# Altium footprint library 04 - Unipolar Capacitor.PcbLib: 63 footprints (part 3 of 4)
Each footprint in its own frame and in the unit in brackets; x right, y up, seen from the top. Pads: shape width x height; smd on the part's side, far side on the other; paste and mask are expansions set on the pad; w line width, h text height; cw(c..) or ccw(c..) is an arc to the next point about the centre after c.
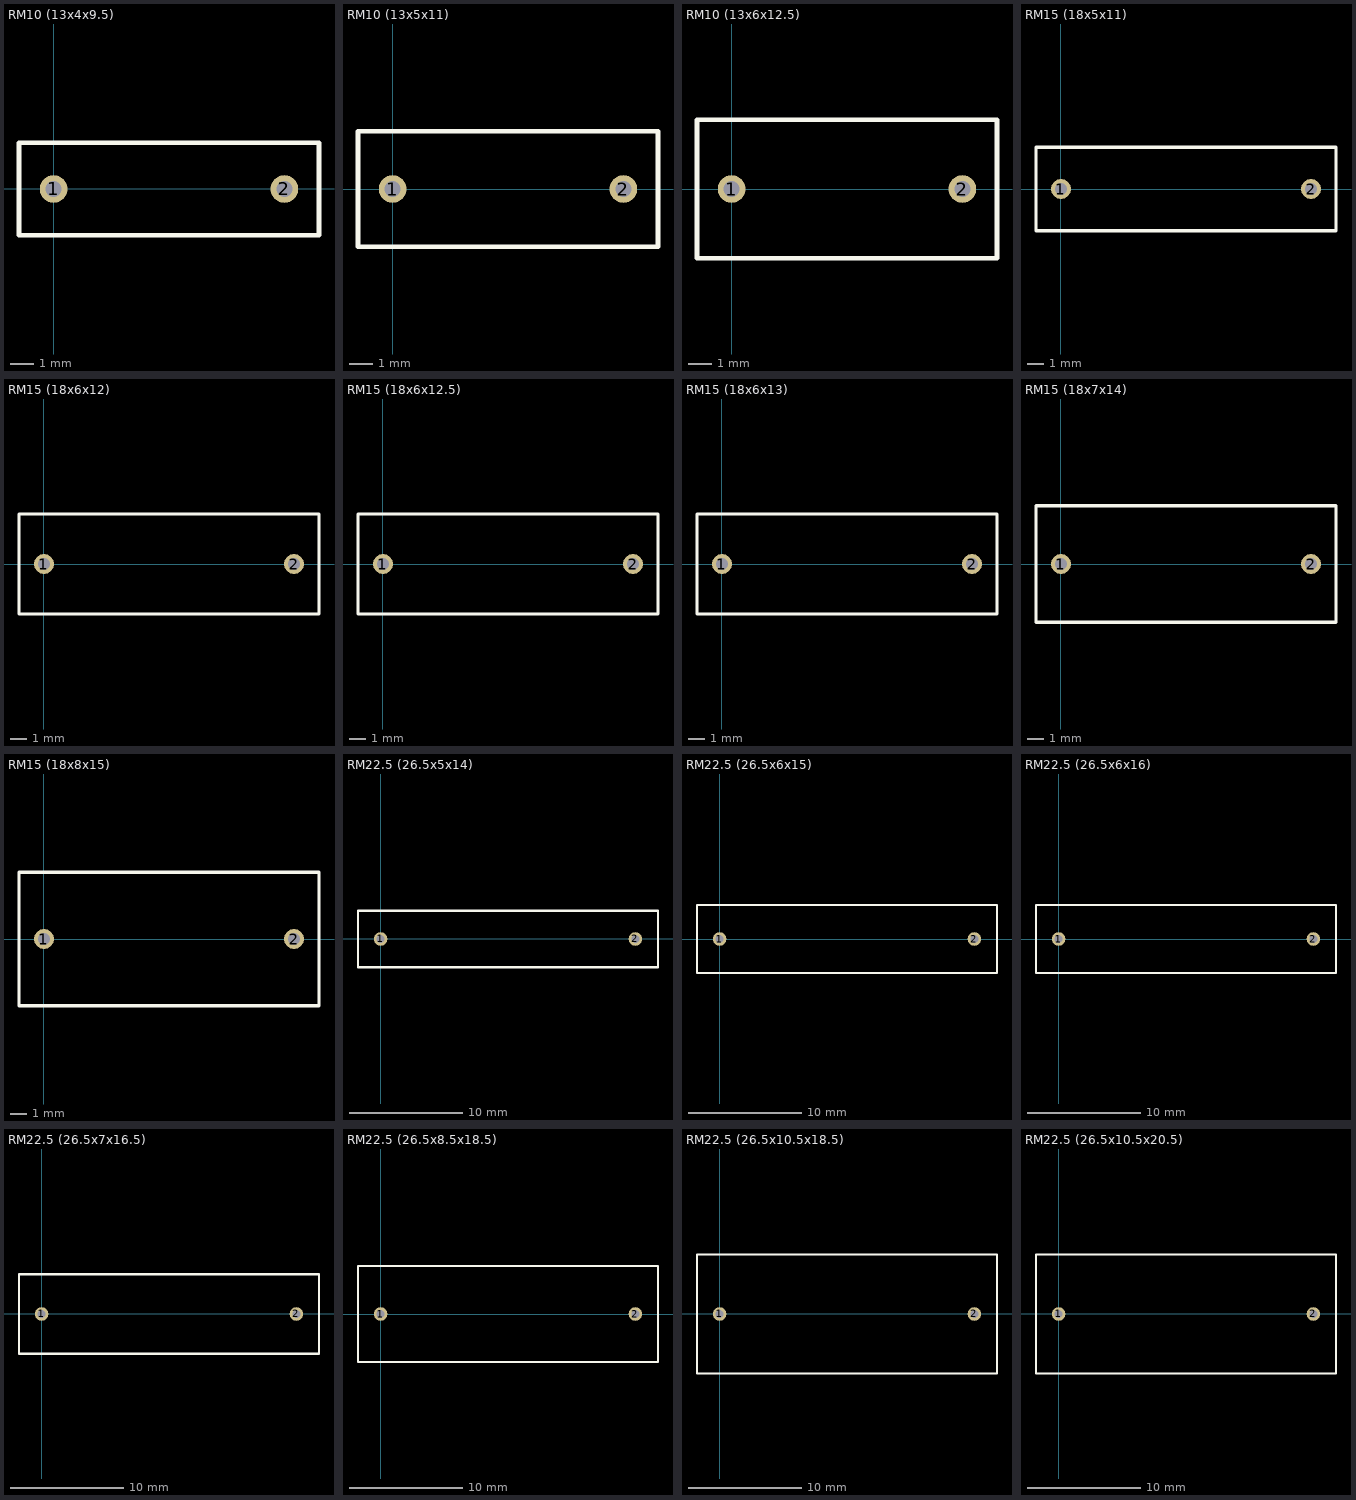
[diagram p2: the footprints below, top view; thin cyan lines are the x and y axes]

## RM10 (13x4x9.5) [mm] "Radial Thumb Capacitor"
height 9.5
pads (2):
  round 1.2 hole 0.7: 1(0,0) 2(10,0)
Top Overlay:
  lines w0.2: -1.5,-2 11.5,-2 11.5,2 -1.5,2 -1.5,-2

## RM10 (13x5x11) [mm] "Radial Thumb Capacitor"
height 11
pads (2):
  round 1.2 hole 0.7: 1(0,0) 2(10,0)
Top Overlay:
  lines w0.2: -1.5,-2.5 11.5,-2.5 11.5,2.5 -1.5,2.5 -1.5,-2.5

## RM10 (13x6x12.5) [mm] "Radial Thumb Capacitor"
height 12.5
pads (2):
  round 1.2 hole 0.7: 1(0,0) 2(10,0)
Top Overlay:
  lines w0.2: -1.5,-3 11.5,-3 11.5,3 -1.5,3 -1.5,-3

## RM15 (18x5x11) [mm] "Radial Thumb Capacitor"
height 11
pads (2):
  round 1.2 hole 0.7: 1(0,0) 2(15,0)
Top Overlay:
  lines w0.2: -1.5,-2.5 16.5,-2.5 16.5,2.5 -1.5,2.5 -1.5,-2.5

## RM15 (18x6x12) [mm] "Radial Thumb Capacitor"
height 12
pads (2):
  round 1.2 hole 0.7: 1(0,0) 2(15,0)
Top Overlay:
  lines w0.2: -1.5,-3 -1.5,3 16.5,3 16.5,-3 -1.5,-3

## RM15 (18x6x12.5) [mm] "Radial Thumb Capacitor"
height 12.5
pads (2):
  round 1.2 hole 0.7: 1(0,0) 2(15,0)
Top Overlay:
  lines w0.2: -1.5,-3 16.5,-3 16.5,3 -1.5,3 -1.5,-3

## RM15 (18x6x13) [mm] "Radial Thumb Capacitor"
height 13
pads (2):
  round 1.2 hole 0.7: 1(0,0) 2(15,0)
Top Overlay:
  lines w0.2: -1.5,-3 -1.5,3 16.5,3 16.5,-3 -1.5,-3

## RM15 (18x7x14) [mm] "Radial Thumb Capacitor"
height 14
pads (2):
  round 1.2 hole 0.7: 1(0,0) 2(15,0)
Top Overlay:
  lines w0.2: -1.5,-3.5 16.5,-3.5 16.5,3.5 -1.5,3.5 -1.5,-3.5

## RM15 (18x8x15) [mm] "Radial Thumb Capacitor"
height 15
pads (2):
  round 1.2 hole 0.7: 1(0,0) 2(15,0)
Top Overlay:
  lines w0.2: -1.5,-4 16.5,-4 16.5,4 -1.5,4 -1.5,-4

## RM22.5 (26.5x5x14) [mm] "Radial Thumb Capacitor"
height 14
pads (2):
  round 1.2 hole 0.7: 1(0,0) 2(22.5,0)
Top Overlay:
  lines w0.2: -2,-2.5 -2,2.5 24.5,2.5 24.5,-2.5 -2,-2.5

## RM22.5 (26.5x6x15) [mm] "Radial Thumb Capacitor"
height 15
pads (2):
  round 1.2 hole 0.7: 1(0,0) 2(22.5,0)
Top Overlay:
  lines w0.2: -2,-3 24.5,-3 24.5,3 -2,3 -2,-3

## RM22.5 (26.5x6x16) [mm] "Radial Thumb Capacitor"
height 16
pads (2):
  round 1.2 hole 0.7: 1(0,0) 2(22.5,0)
Top Overlay:
  lines w0.2: -2,-3 24.5,-3 24.5,3 -2,3 -2,-3

## RM22.5 (26.5x7x16.5) [mm] "Radial Thumb Capacitor"
height 16.5
pads (2):
  round 1.2 hole 0.7: 1(0,0) 2(22.5,0)
Top Overlay:
  lines w0.2: -2,-3.5 24.5,-3.5 24.5,3.5 -2,3.5 -2,-3.5

## RM22.5 (26.5x8.5x18.5) [mm] "Radial Thumb Capacitor"
height 18.5
pads (2):
  round 1.2 hole 0.7: 1(0,0) 2(22.5,0)
Top Overlay:
  lines w0.2: -2,-4.25 24.5,-4.25 24.5,4.25 -2,4.25 -2,-4.25

## RM22.5 (26.5x10.5x18.5) [mm] "Radial Thumb Capacitor"
height 18.5
pads (2):
  round 1.2 hole 0.7: 1(0,0) 2(22.5,0)
Top Overlay:
  lines w0.2: -2,-5.25 24.5,-5.25 24.5,5.25 -2,5.25 -2,-5.25

## RM22.5 (26.5x10.5x20.5) [mm] "Radial Thumb Capacitor"
height 20.5
pads (2):
  round 1.2 hole 0.7: 1(0,0) 2(22.5,0)
Top Overlay:
  lines w0.2: -2,-5.25 24.5,-5.25 24.5,5.25 -2,5.25 -2,-5.25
